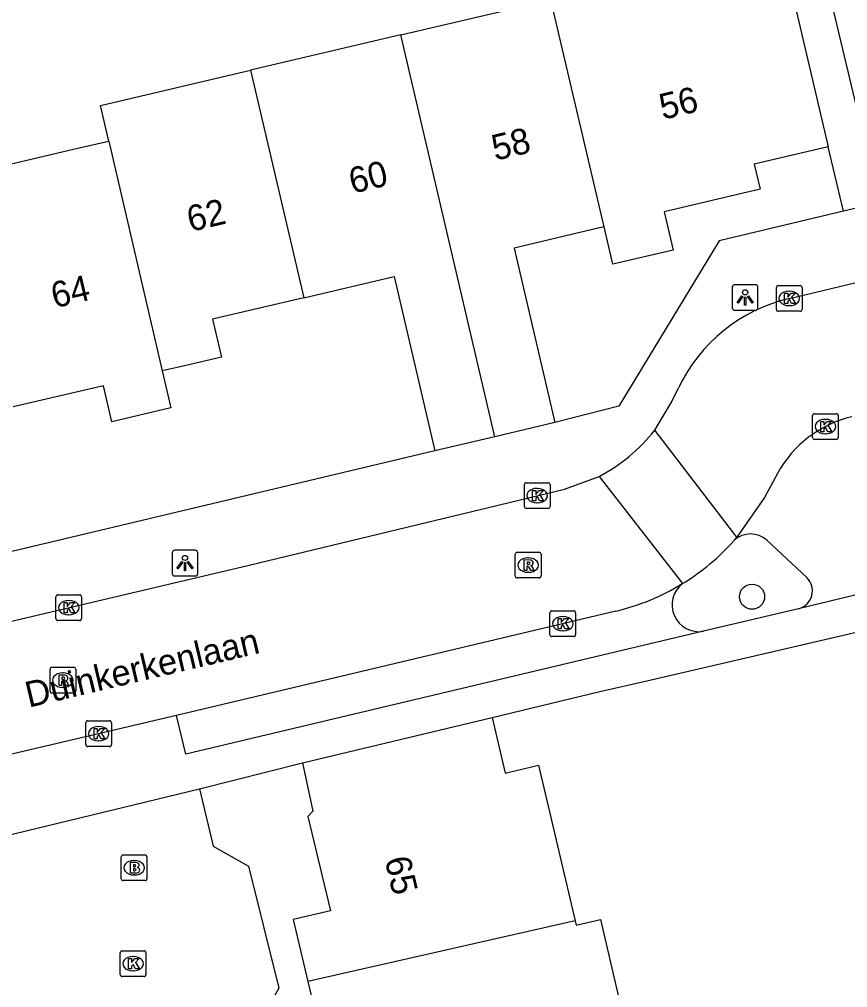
# Model space of a CAD drawing. Extents: x 158474 to 159560, y 388525 to 389605.
# Drawn here: x 159403.64 to 159435.86, y 388678.16 to 388715.8 of the extents above; entities that cross this region are included whole.
import ezdxf

# ---------------------------------------------------------------- set-up
doc = ezdxf.new("R2010")
doc.units = 0
for name, color, linetype in [('IMGEO_Boom', 7, 'Continuous'), ('IMGEO_Brandkraan', 7, 'Continuous'), ('IMGEO_Kolk', 7, 'Continuous'), ('IMGEO_Lichtpunt', 7, 'Continuous'), ('IMGEO_Muur', 7, 'Continuous'), ('IMGEO_Openbare_ruimte_label', 7, 'Continuous'), ('IMGEO_Pand', 7, 'Continuous'), ('IMGEO_Pand_nummerreeks', 7, 'Continuous'), ('IMGEO_Parkeervlak_open', 7, 'Continuous'), ('IMGEO_Rijbaan_lokaal_open', 7, 'Continuous'), ('IMGEO_Rioolput', 7, 'Continuous'), ('IMGEO_Voetpad_open', 7, 'Continuous')]:
    doc.layers.add(name, color=color, linetype=linetype)

msp = doc.modelspace()

# ---------------------------------------------------------------- linework, layer by layer
at = {"layer": 'IMGEO_Boom'}
msp.add_circle((159432.146, 388693.357), 0.489, dxfattribs=at)
at = {"layer": 'IMGEO_Brandkraan'}
for p, q in [((159407.606, 388682.394), (159407.606, 388683.246)), ((159407.681, 388683.32), (159408.533, 388683.32)), ((159408.607, 388683.246), (159408.607, 388682.394)), ((159408.094, 388683.1), (159408.119, 388683.1)), ((159408.117, 388682.54), (159408.092, 388682.54)), ((159408.533, 388682.32), (159407.681, 388682.32))]:
    msp.add_line(p, q, dxfattribs=at)
for points in [[(159407.606, 388682.394), (159407.606, 388683.246)], [(159407.681, 388683.32), (159408.533, 388683.32)], [(159408.607, 388683.246), (159408.607, 388682.394)], [(159407.954, 388683.02), (159407.954, 388682.62), (159408.167, 388682.62)], [(159408.185, 388683.02), (159407.954, 388683.02)], [(159408.133, 388682.939), (159408.079, 388682.939), (159408.079, 388682.863)], [(159408.079, 388682.863), (159408.132, 388682.863)], [(159408.141, 388682.787), (159408.079, 388682.787), (159408.079, 388682.706)], [(159408.079, 388682.706), (159408.141, 388682.706)], [(159408.533, 388682.32), (159407.681, 388682.32)]]:
    msp.add_lwpolyline(points, dxfattribs=at)
for centre, radius, start, end in [((159407.683, 388683.244), 0.0765, 91.552, 178.448), ((159407.683, 388683.244), 0.0765, 91.552, 178.448), ((159408.531, 388683.244), 0.0765, 1.552, 88.448), ((159408.531, 388683.244), 0.0765, 1.552, 88.448), ((159408.134, 388682.901), 0.0379, 267.8285, 90.9355), ((159408.142, 388682.746), 0.0404, 269.8759, 90.5077), ((159408.189, 388682.875), 0.145, 59.4692, 91.5367), ((159408.214, 388682.922), 0.0922, 285.5137, 58.1501), ((159408.219, 388682.73), 0.105, 301.3115, 78.989), ((159407.683, 388682.396), 0.0765, 181.552, 268.448), ((159407.683, 388682.396), 0.0765, 181.552, 268.448), ((159408.173, 388682.871), 0.251, 268.6676, 293.5347), ((159408.531, 388682.396), 0.0765, 271.552, 358.448), ((159408.531, 388682.396), 0.0765, 271.552, 358.448)]:
    msp.add_arc(centre, radius, start, end, dxfattribs=at)
for centre, major_axis, ratio, start_param, end_param in [((159408.093, 388682.82), (-0.387, 0.002), 0.722429, 4.712389, 7.853982), ((159408.118, 388682.82), (-0.39, 0.002), 0.717154, 1.570796, 4.712389)]:
    msp.add_ellipse(centre, major_axis=major_axis, ratio=ratio, start_param=start_param, end_param=end_param, dxfattribs=at)
at = {"layer": 'IMGEO_Kolk'}
for p, q in [((159433.091, 388704.525), (159433.091, 388705.377)), ((159433.166, 388705.451), (159434.018, 388705.451)), ((159434.092, 388705.377), (159434.092, 388704.525)), ((159433.579, 388705.231), (159433.604, 388705.231)), ((159433.602, 388704.671), (159433.577, 388704.671)), ((159434.018, 388704.451), (159433.166, 388704.451)), ((159434.573, 388700.471), (159435.425, 388700.471)), ((159434.498, 388699.545), (159434.498, 388700.397)), ((159434.986, 388700.251), (159435.011, 388700.251)), ((159435.499, 388700.397), (159435.499, 388699.545)), ((159435.009, 388699.691), (159434.984, 388699.691)), ((159435.425, 388699.471), (159434.573, 388699.471)), ((159423.363, 388697.786), (159424.215, 388697.786)), ((159423.288, 388696.86), (159423.288, 388697.712)), ((159423.776, 388697.566), (159423.801, 388697.566)), ((159424.289, 388697.712), (159424.289, 388696.86)), ((159424.215, 388696.786), (159423.363, 388696.786)), ((159423.799, 388697.006), (159423.774, 388697.006)), ((159405.061, 388692.503), (159405.061, 388693.355)), ((159405.136, 388693.429), (159405.988, 388693.429)), ((159406.062, 388693.355), (159406.062, 388692.503)), ((159405.549, 388693.209), (159405.574, 388693.209)), ((159405.572, 388692.649), (159405.547, 388692.649)), ((159424.281, 388691.881), (159424.281, 388692.733)), ((159424.356, 388692.807), (159425.208, 388692.807)), ((159424.769, 388692.587), (159424.794, 388692.587)), ((159425.282, 388692.733), (159425.282, 388691.881)), ((159405.988, 388692.429), (159405.136, 388692.429)), ((159425.208, 388691.807), (159424.356, 388691.807)), ((159424.792, 388692.027), (159424.767, 388692.027)), ((159406.226, 388687.605), (159406.226, 388688.457)), ((159406.301, 388688.531), (159407.153, 388688.531)), ((159407.227, 388688.457), (159407.227, 388687.605)), ((159406.714, 388688.311), (159406.739, 388688.311)), ((159406.737, 388687.751), (159406.712, 388687.751)), ((159407.153, 388687.531), (159406.301, 388687.531)), ((159407.565, 388678.666), (159407.565, 388679.518)), ((159407.64, 388679.592), (159408.492, 388679.592)), ((159408.053, 388679.372), (159408.078, 388679.372)), ((159408.566, 388679.518), (159408.566, 388678.666)), ((159408.492, 388678.592), (159407.64, 388678.592)), ((159408.076, 388678.812), (159408.051, 388678.812))]:
    msp.add_line(p, q, dxfattribs=at)
for points in [[(159433.091, 388704.525), (159433.091, 388705.377)], [(159433.166, 388705.451), (159434.018, 388705.451)], [(159434.092, 388705.377), (159434.092, 388704.525)], [(159433.412, 388705.151), (159433.535, 388705.151), (159433.535, 388705), (159433.665, 388705.151), (159433.829, 388705.151), (159433.683, 388705), (159433.836, 388704.751), (159433.684, 388704.751), (159433.599, 388704.915), (159433.535, 388704.848), (159433.535, 388704.751), (159433.412, 388704.751), (159433.412, 388705.151)], [(159434.018, 388704.451), (159433.166, 388704.451)], [(159434.573, 388700.471), (159435.425, 388700.471)], [(159434.498, 388699.545), (159434.498, 388700.397)], [(159434.819, 388700.171), (159434.942, 388700.171), (159434.942, 388700.02), (159435.072, 388700.171), (159435.236, 388700.171), (159435.09, 388700.02), (159435.243, 388699.771), (159435.091, 388699.771), (159435.006, 388699.935), (159434.942, 388699.868), (159434.942, 388699.771), (159434.819, 388699.771), (159434.819, 388700.171)], [(159435.499, 388700.397), (159435.499, 388699.545)], [(159435.425, 388699.471), (159434.573, 388699.471)], [(159423.363, 388697.786), (159424.215, 388697.786)], [(159423.288, 388696.86), (159423.288, 388697.712)], [(159423.609, 388697.486), (159423.732, 388697.486), (159423.732, 388697.335), (159423.862, 388697.486), (159424.026, 388697.486), (159423.88, 388697.335), (159424.033, 388697.086), (159423.881, 388697.086), (159423.796, 388697.25), (159423.732, 388697.183), (159423.732, 388697.086), (159423.609, 388697.086), (159423.609, 388697.486)], [(159424.289, 388697.712), (159424.289, 388696.86)], [(159424.215, 388696.786), (159423.363, 388696.786)], [(159405.061, 388692.503), (159405.061, 388693.355)], [(159405.136, 388693.429), (159405.988, 388693.429)], [(159406.062, 388693.355), (159406.062, 388692.503)], [(159405.382, 388693.129), (159405.505, 388693.129), (159405.505, 388692.978), (159405.635, 388693.129), (159405.799, 388693.129), (159405.653, 388692.978), (159405.806, 388692.729), (159405.654, 388692.729), (159405.569, 388692.893), (159405.505, 388692.826), (159405.505, 388692.729), (159405.382, 388692.729), (159405.382, 388693.129)], [(159424.281, 388691.881), (159424.281, 388692.733)], [(159424.356, 388692.807), (159425.208, 388692.807)], [(159425.282, 388692.733), (159425.282, 388691.881)], [(159405.988, 388692.429), (159405.136, 388692.429)], [(159424.602, 388692.507), (159424.725, 388692.507), (159424.725, 388692.356), (159424.855, 388692.507), (159425.019, 388692.507), (159424.873, 388692.356), (159425.026, 388692.107), (159424.874, 388692.107), (159424.789, 388692.271), (159424.725, 388692.204), (159424.725, 388692.107), (159424.602, 388692.107), (159424.602, 388692.507)], [(159425.208, 388691.807), (159424.356, 388691.807)], [(159406.226, 388687.605), (159406.226, 388688.457)], [(159406.301, 388688.531), (159407.153, 388688.531)], [(159407.227, 388688.457), (159407.227, 388687.605)], [(159406.547, 388688.231), (159406.67, 388688.231), (159406.67, 388688.08), (159406.8, 388688.231), (159406.964, 388688.231), (159406.818, 388688.08), (159406.971, 388687.831), (159406.819, 388687.831), (159406.734, 388687.995), (159406.67, 388687.928), (159406.67, 388687.831), (159406.547, 388687.831), (159406.547, 388688.231)], [(159407.153, 388687.531), (159406.301, 388687.531)], [(159407.565, 388678.666), (159407.565, 388679.518)], [(159407.64, 388679.592), (159408.492, 388679.592)], [(159408.566, 388679.518), (159408.566, 388678.666)], [(159407.886, 388679.292), (159408.009, 388679.292), (159408.009, 388679.141), (159408.139, 388679.292), (159408.303, 388679.292), (159408.157, 388679.141), (159408.31, 388678.892), (159408.158, 388678.892), (159408.073, 388679.056), (159408.009, 388678.989), (159408.009, 388678.892), (159407.886, 388678.892), (159407.886, 388679.292)], [(159408.492, 388678.592), (159407.64, 388678.592)]]:
    msp.add_lwpolyline(points, dxfattribs=at)
for centre, start, end in [((159433.168, 388705.375), 91.552, 178.448), ((159433.168, 388705.375), 91.552, 178.448), ((159434.016, 388705.375), 1.552, 88.448), ((159434.016, 388705.375), 1.552, 88.448), ((159433.168, 388704.527), 181.552, 268.448), ((159433.168, 388704.527), 181.552, 268.448), ((159434.016, 388704.527), 271.552, 358.448), ((159434.016, 388704.527), 271.552, 358.448), ((159434.575, 388700.395), 91.552, 178.448), ((159434.575, 388700.395), 91.552, 178.448), ((159435.423, 388700.395), 1.552, 88.448), ((159435.423, 388700.395), 1.552, 88.448), ((159434.575, 388699.547), 181.552, 268.448), ((159434.575, 388699.547), 181.552, 268.448), ((159435.423, 388699.547), 271.552, 358.448), ((159435.423, 388699.547), 271.552, 358.448), ((159423.365, 388697.71), 91.552, 178.448), ((159423.365, 388697.71), 91.552, 178.448), ((159424.213, 388697.71), 1.552, 88.448), ((159424.213, 388697.71), 1.552, 88.448), ((159423.365, 388696.862), 181.552, 268.448), ((159423.365, 388696.862), 181.552, 268.448), ((159424.213, 388696.862), 271.552, 358.448), ((159424.213, 388696.862), 271.552, 358.448), ((159405.138, 388693.353), 91.552, 178.448), ((159405.138, 388693.353), 91.552, 178.448), ((159405.986, 388693.353), 1.552, 88.448), ((159405.986, 388693.353), 1.552, 88.448), ((159424.358, 388692.731), 91.552, 178.448), ((159424.358, 388692.731), 91.552, 178.448), ((159425.206, 388692.731), 1.552, 88.448), ((159425.206, 388692.731), 1.552, 88.448), ((159405.138, 388692.505), 181.552, 268.448), ((159405.138, 388692.505), 181.552, 268.448), ((159405.986, 388692.505), 271.552, 358.448), ((159405.986, 388692.505), 271.552, 358.448), ((159424.358, 388691.883), 181.552, 268.448), ((159424.358, 388691.883), 181.552, 268.448), ((159425.206, 388691.883), 271.552, 358.448), ((159425.206, 388691.883), 271.552, 358.448), ((159406.303, 388688.455), 91.552, 178.448), ((159406.303, 388688.455), 91.552, 178.448), ((159407.151, 388688.455), 1.552, 88.448), ((159407.151, 388688.455), 1.552, 88.448), ((159406.303, 388687.607), 181.552, 268.448), ((159406.303, 388687.607), 181.552, 268.448), ((159407.151, 388687.607), 271.552, 358.448), ((159407.151, 388687.607), 271.552, 358.448), ((159407.642, 388679.516), 91.552, 178.448), ((159407.642, 388679.516), 91.552, 178.448), ((159408.49, 388679.516), 1.552, 88.448), ((159408.49, 388679.516), 1.552, 88.448), ((159407.642, 388678.668), 181.552, 268.448), ((159407.642, 388678.668), 181.552, 268.448), ((159408.49, 388678.668), 271.552, 358.448), ((159408.49, 388678.668), 271.552, 358.448)]:
    msp.add_arc(centre, 0.0765, start, end, dxfattribs=at)
for centre, major_axis, ratio, start_param, end_param in [((159433.578, 388704.951), (-0.387, 0.002), 0.722429, 4.712389, 7.853982), ((159433.603, 388704.951), (-0.39, 0.002), 0.717154, 1.570796, 4.712389), ((159434.985, 388699.971), (-0.387, 0.002), 0.722429, 4.712389, 7.853982), ((159435.01, 388699.971), (-0.39, 0.002), 0.717154, 1.570796, 4.712389), ((159423.775, 388697.286), (-0.387, 0.002), 0.722429, 4.712389, 7.853982), ((159423.8, 388697.286), (-0.39, 0.002), 0.717154, 1.570796, 4.712389), ((159405.548, 388692.929), (-0.387, 0.002), 0.722429, 4.712389, 7.853982), ((159405.573, 388692.929), (-0.39, 0.002), 0.717154, 1.570796, 4.712389), ((159424.768, 388692.307), (-0.387, 0.002), 0.722429, 4.712389, 7.853982), ((159424.793, 388692.307), (-0.39, 0.002), 0.717154, 1.570796, 4.712389), ((159406.713, 388688.031), (-0.387, 0.002), 0.722429, 4.712389, 7.853982), ((159406.738, 388688.031), (-0.39, 0.002), 0.717154, 1.570796, 4.712389), ((159408.052, 388679.092), (-0.387, 0.002), 0.722429, 4.712389, 7.853982), ((159408.077, 388679.092), (-0.39, 0.002), 0.717154, 1.570796, 4.712389)]:
    msp.add_ellipse(centre, major_axis=major_axis, ratio=ratio, start_param=start_param, end_param=end_param, dxfattribs=at)
at = {"layer": 'IMGEO_Lichtpunt'}
for p, q in [((159431.377, 388705.39), (159431.377, 388704.583)), ((159431.377, 388705.39), (159431.377, 388704.583)), ((159432.279, 388705.485), (159431.471, 388705.485)), ((159432.279, 388705.485), (159431.471, 388705.485)), ((159432.373, 388704.583), (159432.373, 388705.39)), ((159432.373, 388704.583), (159432.373, 388705.39)), ((159431.471, 388704.489), (159432.279, 388704.489)), ((159431.471, 388704.489), (159432.279, 388704.489)), ((159410.489, 388695.161), (159409.681, 388695.161)), ((159410.489, 388695.161), (159409.681, 388695.161)), ((159409.587, 388695.066), (159409.587, 388694.259)), ((159409.587, 388695.066), (159409.587, 388694.259)), ((159410.583, 388694.259), (159410.583, 388695.066)), ((159410.583, 388694.259), (159410.583, 388695.066)), ((159409.681, 388694.165), (159410.489, 388694.165)), ((159409.681, 388694.165), (159410.489, 388694.165))]:
    msp.add_line(p, q, dxfattribs=at)
for points in [[(159431.751, 388705.054), (159431.79, 388705.026), (159431.602, 388704.764), (159431.564, 388704.791), (159431.751, 388705.054)], [(159431.853, 388705.006), (159431.9, 388705.006), (159431.9, 388704.684), (159431.853, 388704.684), (159431.853, 388705.006)], [(159431.963, 388705.026), (159432.001, 388705.053), (159432.188, 388704.791), (159432.149, 388704.763), (159431.963, 388705.026)], [(159409.961, 388694.73), (159410, 388694.702), (159409.812, 388694.44), (159409.774, 388694.467), (159409.961, 388694.73)], [(159410.063, 388694.682), (159410.11, 388694.682), (159410.11, 388694.36), (159410.063, 388694.36), (159410.063, 388694.682)], [(159410.173, 388694.702), (159410.211, 388694.729), (159410.398, 388694.467), (159410.359, 388694.439), (159410.173, 388694.702)]]:
    msp.add_lwpolyline(points, dxfattribs=at)
for centre in [(159431.876, 388705.188), (159410.086, 388694.864)]:
    msp.add_circle(centre, 0.0994, dxfattribs=at)
for centre, start, end in [((159431.471, 388705.39), 90, 180), ((159431.471, 388705.39), 90, 180), ((159432.279, 388705.39), 0, 90), ((159432.279, 388705.39), 0, 90), ((159431.471, 388704.583), 180, 270), ((159431.471, 388704.583), 180, 270), ((159432.279, 388704.583), 270, 0), ((159432.279, 388704.583), 270, 360), ((159409.681, 388695.066), 90, 180), ((159409.681, 388695.066), 90, 180), ((159410.489, 388695.066), 0, 90), ((159410.489, 388695.066), 0, 90), ((159409.681, 388694.259), 180, 270), ((159409.681, 388694.259), 180, 270), ((159410.489, 388694.259), 270, 0), ((159410.489, 388694.259), 270, 360)]:
    msp.add_arc(centre, 0.0946, start, end, dxfattribs=at)
at = {"layer": 'IMGEO_Muur'}
for points in [[(159426.229, 388689.666), (159428.053, 388690.09)], [(159422.033, 388688.657), (159426.229, 388689.666)]]:
    msp.add_lwpolyline(points, dxfattribs=at)
at = {"layer": 'IMGEO_Pand'}
for points in [[(159433.412, 388718.04), (159433.481, 388717.747), (159433.96, 388715.708), (159435.103, 388710.84)], [(159418.48, 388715.197), (159424.318, 388716.568)], [(159426.388, 388707.732), (159424.318, 388716.568)], [(159418.48, 388715.197), (159412.636, 388713.824)], [(159422.143, 388699.577), (159418.48, 388715.197)], [(159407.119, 388711.071), (159406.797, 388712.452), (159412.636, 388713.824)], [(159412.636, 388713.824), (159414.71, 388704.978)], [(159401.286, 388709.701), (159405.801, 388710.761), (159406.941, 388711.029), (159407.119, 388711.071)], [(159407.119, 388711.071), (159409.199, 388702.132)], [(159435.103, 388710.84), (159432.228, 388710.165), (159432.456, 388709.194), (159428.724, 388708.317), (159429.074, 388706.827), (159426.729, 388706.277), (159426.388, 388707.732)], [(159426.388, 388707.732), (159426.214, 388707.691), (159425.394, 388707.499), (159422.885, 388706.909), (159424.479, 388700.126)], [(159414.71, 388704.978), (159418.217, 388705.802), (159419.808, 388699.029)], [(159414.71, 388704.978), (159411.155, 388704.143), (159411.5, 388702.672), (159410.066, 388702.336), (159409.373, 388702.173), (159409.199, 388702.132)], [(159409.199, 388702.132), (159409.534, 388700.695), (159407.244, 388700.157), (159406.915, 388701.559), (159403.401, 388700.734)], [(159424.479, 388700.126), (159422.143, 388699.577)], [(159422.143, 388699.577), (159419.808, 388699.029)], [(159414.657, 388686.898), (159422.033, 388688.657)], [(159422.033, 388688.657), (159422.539, 388686.497), (159423.844, 388686.802), (159425.263, 388680.76)], [(159414.657, 388686.898), (159415.055, 388685.017), (159414.869, 388684.813), (159415.746, 388681.143), (159414.294, 388680.806), (159414.864, 388678.4)], [(159425.263, 388680.76), (159414.864, 388678.4)], [(159425.263, 388680.76), (159425.304, 388680.587), (159426.244, 388680.807), (159427.561, 388675.181), (159425.201, 388674.629)], [(159414.864, 388678.4), (159415.68, 388674.957), (159414.212, 388674.613), (159414.789, 388672.163)]]:
    msp.add_lwpolyline(points, dxfattribs=at)
at = {"layer": 'IMGEO_Parkeervlak_open'}
msp.add_lwpolyline([(159434.276, 388694.101), (159432.716, 388695.548)], dxfattribs=at)
for centre, radius, start, end in [((159432.085, 388694.869), 0.927, 47.0877, 132.9123), ((159433.773, 388693.586), 0.72, 284.9095, 45.6406), ((159430.078, 388693.04), 1.044, 127.8944, 279.6398)]:
    msp.add_arc(centre, radius, start, end, dxfattribs=at)
at = {"layer": 'IMGEO_Rijbaan_lokaal_open'}
for points in [[(159433.596, 388704.953), (159438.14, 388706.032)], [(159428.357, 388699.832), (159429.016, 388700.914), (159429.282, 388701.47)], [(159431.559, 388695.668), (159428.357, 388699.832)], [(159400.968, 388691.843), (159412.576, 388694.588), (159424.854, 388697.543), (159426.198, 388698.035)], [(159426.198, 388698.035), (159429.437, 388693.864)], [(159433.135, 388698.143), (159432.628, 388697.215), (159431.559, 388695.668)], [(159431.559, 388695.668), (159431.454, 388695.548)], [(159426.847, 388692.797), (159414.62, 388689.888), (159409.757, 388688.743)], [(159409.757, 388688.743), (159402.12, 388686.945)], [(159402.664, 388683.954), (159410.645, 388685.894)], [(159410.645, 388685.894), (159411.188, 388683.663), (159412.551, 388682.879), (159413.737, 388678.145), (159411.255, 388673.704), (159413.892, 388663.207), (159417.902, 388660.407), (159419.033, 388656.042), (159418.134, 388654.399), (159418.765, 388652.043)]]:
    msp.add_lwpolyline(points, dxfattribs=at)
for centre, radius, start, end in [((159435.079, 388698.703), 6.424, 103.3498, 154.4831), ((159437.056, 388696.006), 4.465, 103.2789, 151.4112), ((159423.194, 388703.84), 6.536, 297.363, 322.1802), ((159424.811, 388701.454), 8.889, 301.3589, 318.3583), ((159424.79, 388701.466), 8.91, 283.3461, 301.4342)]:
    msp.add_arc(centre, radius, start, end, dxfattribs=at)
at = {"layer": 'IMGEO_Rioolput'}
for p, q in [((159422.935, 388694.158), (159422.935, 388695.01)), ((159423.01, 388695.084), (159423.862, 388695.084)), ((159423.423, 388694.864), (159423.448, 388694.864)), ((159423.936, 388695.01), (159423.936, 388694.158)), ((159423.862, 388694.084), (159423.01, 388694.084)), ((159423.446, 388694.304), (159423.421, 388694.304)), ((159404.836, 388689.686), (159404.836, 388690.538)), ((159404.911, 388690.612), (159405.763, 388690.612)), ((159405.324, 388690.392), (159405.349, 388690.392)), ((159405.837, 388690.538), (159405.837, 388689.686)), ((159405.763, 388689.612), (159404.911, 388689.612)), ((159405.347, 388689.832), (159405.322, 388689.832))]:
    msp.add_line(p, q, dxfattribs=at)
for points in [[(159422.935, 388694.158), (159422.935, 388695.01)], [(159423.01, 388695.084), (159423.862, 388695.084)], [(159423.524, 388694.782), (159423.272, 388694.784), (159423.272, 388694.384)], [(159423.936, 388695.01), (159423.936, 388694.158)], [(159423.272, 388694.384), (159423.396, 388694.384), (159423.396, 388694.546), (159423.407, 388694.546)], [(159423.45, 388694.703), (159423.396, 388694.703), (159423.396, 388694.622)], [(159423.396, 388694.622), (159423.448, 388694.622)], [(159423.454, 388694.517), (159423.525, 388694.384), (159423.665, 388694.384), (159423.6, 388694.51)], [(159423.862, 388694.084), (159423.01, 388694.084)], [(159404.836, 388689.686), (159404.836, 388690.538)], [(159404.911, 388690.612), (159405.763, 388690.612)], [(159405.425, 388690.31), (159405.173, 388690.312), (159405.173, 388689.912)], [(159405.837, 388690.538), (159405.837, 388689.686)], [(159405.173, 388689.912), (159405.297, 388689.912), (159405.297, 388690.074), (159405.308, 388690.074)], [(159405.351, 388690.231), (159405.297, 388690.231), (159405.297, 388690.15)], [(159405.297, 388690.15), (159405.349, 388690.15)], [(159405.355, 388690.045), (159405.426, 388689.912), (159405.566, 388689.912), (159405.501, 388690.038)], [(159405.763, 388689.612), (159404.911, 388689.612)]]:
    msp.add_lwpolyline(points, dxfattribs=at)
for centre, radius, start, end in [((159423.012, 388695.008), 0.0765, 91.552, 178.448), ((159423.012, 388695.008), 0.0765, 91.552, 178.448), ((159423.523, 388694.672), 0.109, 350.3612, 89.416), ((159423.86, 388695.008), 0.0765, 1.552, 88.448), ((159423.86, 388695.008), 0.0765, 1.552, 88.448), ((159423.406, 388694.493), 0.0533, 26.0293, 88.6989), ((159423.432, 388694.811), 0.19, 274.7715, 282.9687), ((159423.456, 388694.607), 0.0964, 77.0061, 93.1865), ((159423.47, 388694.664), 0.0378, 276.6634, 79.6772), ((159423.521, 388694.672), 0.112, 277.5842, 350.9817), ((159423.505, 388694.457), 0.108, 29.5134, 73.7905), ((159423.012, 388694.16), 0.0765, 181.552, 268.448), ((159423.012, 388694.16), 0.0765, 181.552, 268.448), ((159423.86, 388694.16), 0.0765, 271.552, 358.448), ((159423.86, 388694.16), 0.0765, 271.552, 358.448), ((159404.913, 388690.536), 0.0765, 91.552, 178.448), ((159404.913, 388690.536), 0.0765, 91.552, 178.448), ((159405.424, 388690.2), 0.109, 350.3612, 89.416), ((159405.761, 388690.536), 0.0765, 1.552, 88.448), ((159405.761, 388690.536), 0.0765, 1.552, 88.448), ((159405.307, 388690.021), 0.0533, 26.0293, 88.6989), ((159405.333, 388690.339), 0.19, 274.7715, 282.9687), ((159405.357, 388690.135), 0.0964, 77.0061, 93.1865), ((159405.371, 388690.192), 0.0378, 276.6634, 79.6772), ((159405.422, 388690.2), 0.112, 277.5842, 350.9817), ((159405.406, 388689.985), 0.108, 29.5134, 73.7905), ((159404.913, 388689.688), 0.0765, 181.552, 268.448), ((159404.913, 388689.688), 0.0765, 181.552, 268.448), ((159405.761, 388689.688), 0.0765, 271.552, 358.448), ((159405.761, 388689.688), 0.0765, 271.552, 358.448)]:
    msp.add_arc(centre, radius, start, end, dxfattribs=at)
for centre, major_axis, ratio, start_param, end_param in [((159423.422, 388694.584), (-0.387, 0.002), 0.722429, 4.712389, 7.853982), ((159423.447, 388694.584), (-0.39, 0.002), 0.717154, 1.570796, 4.712389), ((159405.323, 388690.112), (-0.387, 0.002), 0.722429, 4.712389, 7.853982), ((159405.348, 388690.112), (-0.39, 0.002), 0.717154, 1.570796, 4.712389)]:
    msp.add_ellipse(centre, major_axis=major_axis, ratio=ratio, start_param=start_param, end_param=end_param, dxfattribs=at)
at = {"layer": 'IMGEO_Voetpad_open'}
for points in [[(159432.128, 388729.477), (159437.093, 388708.671)], [(159435.698, 388708.339), (159435.103, 388710.84)], [(159435.698, 388708.339), (159430.871, 388707.19), (159426.969, 388700.763), (159424.479, 388700.126)], [(159437.093, 388708.671), (159435.698, 388708.339)], [(159440.054, 388701.305), (159441.2, 388696.489), (159438.303, 388695.8), (159436.362, 388693.462), (159433.958, 388692.891)], [(159419.808, 388699.029), (159389.445, 388691.806)], [(159433.958, 388692.891), (159430.253, 388692.011)], [(159422.033, 388688.657), (159426.229, 388689.666), (159428.053, 388690.09), (159439.944, 388692.851)], [(159430.253, 388692.011), (159410.118, 388687.229), (159409.757, 388688.743)], [(159410.645, 388685.894), (159414.657, 388686.898)]]:
    msp.add_lwpolyline(points, dxfattribs=at)

# ---------------------------------------------------------------- texts
at = {"layer": 'IMGEO_Openbare_ruimte_label'}
msp.add_text('Duinkerkenlaan', height=1, rotation=13.2996, dxfattribs=at).set_placement((159404.007, 388689.041))
at = {"layer": 'IMGEO_Pand_nummerreeks'}
for s, rotation, p in [('56', 13.3213, (159428.672, 388711.894)), ('58', 13.3213, (159422.152, 388710.299)), ('60', 13.3214, (159416.597, 388709.016)), ('62', 13.3213, (159410.296, 388707.533)), ('64', 13.3213, (159405.011, 388704.566)), ('65', 283.3606, (159417.847, 388683.143))]:
    msp.add_text(s, height=1, rotation=rotation, dxfattribs=at).set_placement(p)

doc.saveas('drawing.dxf')
